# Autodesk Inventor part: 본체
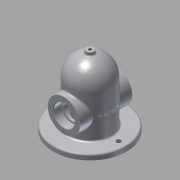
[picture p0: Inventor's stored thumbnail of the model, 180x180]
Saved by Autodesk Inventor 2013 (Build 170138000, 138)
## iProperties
Created: 2019-11
Part Number: 본체
Material: 알루미늄 6061
Document SubType Name: Modeling
Designer: Administrator
Density: 2.71 g/cm^3
Mass: 1110.24 g
Surface Area: 883.324 cm^2
Volume: 409.682 cm^3
Author: Administrator
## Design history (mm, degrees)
sketch "스케치1"
  geometry: C1 r 70 at (0, 0); 1 further point
  constraints: 1 centre point, 1 coincident
  dimensions: "d0" = 140 diameter of C1
extrude "돌출1" new body sketch "스케치1" distance "d2" = 10; taper "d3" = 0 deg
sketch "스케치3"
  geometry: C1 r 70 at (0, 0) reference; C2 r 40 at (0, 0)
  constraints: 1 centre point, 1 coincident
  dimensions: "d12" = 80 diameter of C2
extrude "돌출2" join sketch "스케치3" distance "d14" = 120; taper "d15" = 0 deg
sketch "스케치4"
  geometry: L1 (0, 0)-(-55, 0); L2 (0, 0)-(55, 0); C1 r 70 at (0, 0) reference; C2 r 4.5 at (-55, 0); C3 r 4.5 at (55, 0); A1 r 55 centre (0, 0) between (-55, 0) and (55, 0)
  constraints: 4 end point, 3 centre point, 3 coincident, 2 point on circle, 1 collinear, 1 equal radius, 1 horizontal
  dimensions: "d17" = 110 diameter of A1; "d20" = 9 diameter of C2
extrude "돌출3" cut sketch "스케치4" distance "d21" = 10; taper "d22" = 0 deg
sketch "스케치5"
  geometry: C1 r 70 at (0, 0) reference; C2 r 30 at (0, 0)
  constraints: 1 centre point, 1 coincident
  dimensions: "d23" = 60 diameter of C2
extrude "돌출4" cut sketch "스케치5" distance "d25" = 120; taper "d26" = 0 deg
node "작업 평면1"
sketch "스케치6"
  geometry: L1 (0, 0)-(0, 50); L2 (-70, 0)-(70, 0) reference; C1 r 31 at (0, 50)
  constraints: 2 end point, 1 centre point, 1 coincident, 1 perpendicular
  dimensions: "d29" = 50 distance of L1.start L1.end; "d30" = 62 diameter of C1
extrude "돌출5" join sketch "스케치6" stored distance "d31" = 120; taper "d32" = 0 deg
node "작업 평면2"
sketch "스케치7"
  geometry: L1 (0, 0)-(0, 50); C1 r 31 at (0, 50)
  constraints: 2 end point, 1 centre point, 1 coincident, 1 vertical
  dimensions: "d34" = 50 distance of L1.start L1.end; "d35" = 62 diameter of C1
extrude "돌출6" join sketch "스케치7" stored distance "d36" = 120; taper "d37" = 0 deg
sketch "스케치8"
  geometry: C1 r 31 at (0, 0) reference; C2 r 20 at (0, 0); 1 further point
  constraints: 1 centre point, 1 coincident
  dimensions: "d38" = 40 diameter of C2
extrude "돌출7" cut sketch "스케치8" distance "d40" = 15; taper "d41" = 0 deg
sketch "스케치9"
  geometry: C1 r 31 at (0, 0) reference; C2 r 20 at (0, 0); 1 further point
  constraints: 1 centre point, 1 coincident
  dimensions: "d42" = 40 diameter of C2
extrude "돌출8" cut sketch "스케치9" distance "d44" = 15; taper "d45" = 0 deg
sketch "스케치10"
  geometry: C1 r 20 at (0, 0) reference; C2 r 16.5 at (0, 0); 1 further point
  constraints: 1 centre point, 1 coincident
  dimensions: "d46" = 33 diameter of C2
extrude "돌출9" cut sketch "스케치10" stored distance "d48" = 15; taper "d49" = 0 deg
sketch "스케치11"
  geometry: C1 r 20 at (0, 0) reference; C2 r 16.5 at (0, 0); 1 further point
  constraints: 1 centre point, 1 coincident
  dimensions: "d50" = 33 diameter of C2
extrude "돌출10" cut sketch "스케치11" stored distance "d52" = 15; taper "d53" = 0 deg
fillet "모깎기3" dims "d55" = 40
fillet "모깎기4" dims "d56" = 30
node "작업 평면4"
sketch "스케치12"
  geometry: C1 r 7.5 at (0, 0); 1 further point
  constraints: 1 centre point, 1 coincident
  dimensions: "d58" = 15 diameter of C1
extrude "돌출11" join sketch "스케치12" stored distance "d60" = 15; taper "d61" = 0 deg
sketch "스케치13"
  geometry: C1 r 7.5 at (0, 0) reference
hole "구멍1" sketch "스케치13" at (0, 0) diameter "d62" = 5.188; stored, may be unused: countersink angle "d66" = 90 deg, drill point angle "d68" = 0 deg; dims "d63" = 6, "d64" = 4, "d65" = 2, "d67" = 8
sketch "스케치14" dims "d44" = 15, "d45" = 0
  geometry: L1 (0, 0)-(0, 26); L2 (0, 0)-(0, -26); L3 (0, 0)-(-26, 0); L4 (0, 0)-(26, 0); C1 r 31 at (0, 0) reference; A1 r 26 centre (0, 0) between (0, 26) and (0, -26); 1 further point
  constraints: 8 end point, 4 point on circle, 2 collinear, 1 centre point, 1 coincident, 1 perpendicular, 1 vertical
  dimensions: "d69" = 52 diameter of A1
hole "구멍2" sketch "스케치14" at (0, 26), (-26, 0), (0, -26), (26, 0) diameter "d71" = 3.242; stored, may be unused: countersink angle "d75" = 90 deg, drill point angle "d77" = 118 deg; dims "d72" = 8, "d73" = 4, "d74" = 2, "d76" = 10
sketch "스케치15" dims "d78" = 52
  geometry: L1 (0, 0)-(0, 26); L2 (0, 0)-(-26, 0); L3 (0, 0)-(26, 0); L4 (0, 0)-(0, -26); C1 r 31 at (0, 0) reference
  constraints: 8 end point, 2 perpendicular, 1 coincident, 1 collinear, 1 horizontal alignment, 1 vertical, 2 other
hole "구멍3" sketch "스케치15" at (0, -26), (26, 0), (0, 26), (-26, 0) diameter "d80" = 3.242; stored, may be unused: countersink angle "d84" = 90 deg, drill point angle "d86" = 118 deg; dims "d81" = 8, "d82" = 4, "d83" = 2, "d85" = 10
chamfer "모따기1" distance "d87" = 1; stored, may be unused: second distance "d88" = 2, angle "d89" = 45 deg
chamfer "모따기2" distance "d90" = 1; stored, may be unused: second distance "d91" = 2, angle "d92" = 45 deg
fillet "모깎기5" dims "d93" = 0.3, "d94" = 3
node "작업 평면5"
sketch "스케치17"
  geometry: L1 (0, -10)-(0, 40); L2 (30, -10)-(-30, -10) reference; L3 (-19.974, 42.858)-(20.417, 42.858); L4 (20.417, 42.858)-(20.417, 36.878); L5 (20.417, 36.878)-(-19.974, 36.878); L6 (-19.974, 36.878)-(-19.974, 42.858); 1 further point
  constraints: 2 end point, 1 perpendicular, 2 other
  dimensions: "d96" = 50 distance of L1.start L1.end
feature "엠보싱1" sketch "스케치17" dims "d97" = 0.5, "d98" = 0
node "솔리드1"
other parameters: "d57" = 135
